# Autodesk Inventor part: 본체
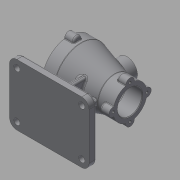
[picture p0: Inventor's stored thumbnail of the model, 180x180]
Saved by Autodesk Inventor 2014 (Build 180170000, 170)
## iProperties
Created: 2020-12
Part Number: 본체
Material: Generic
Document SubType Name: Modeling
Designer: kh
Density: 1 g/cm^3
Appearance: Default
Author: kh
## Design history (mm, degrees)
sketch "Sketch1"
  geometry: L1 (-65, -50)-(65, -50); L2 (65, -50)-(65, 50); L3 (65, 50)-(-65, 50); L4 (-65, 50)-(-65, -50); L5 (-65, -50)-(65, 50); L6 (65, -50)-(-65, 50); 1 further point
  constraints: 12 end point, 2 midpoint, 2 parallel, 1 horizontal, 1 perpendicular
  dimensions: "d0" = 130 distance of L2.end L3.end; "d1" = 100 distance of L1.end L2.end
extrude "Extrusion1" new body sketch "Sketch1" distance "d2" = 12; taper "d3" = 0 deg
sketch "Sketch2"
  geometry: L1 (-70.278, 82)-(64.917, 82); L2 (65, 0)-(-65, 0) reference; L3 (-50, 82)-(-50, 126); L4 (-50, 126)-(-30, 126); L5 (-30, 126)-(25, 109.5); L6 (25, 109.5)-(50, 109.5); L7 (50, 109.5)-(50, 82); L8 (-50, 82)-(50, 82); 1 further point
  constraints: 14 end point, 3 perpendicular, 2 point on line, 1 collinear, 1 horizontal, 1 parallel
  dimensions: "d4" = 82 distance between parallel lines of L2 L1; "d5" = 88 diameter of L4 L1; "d6" = 55 diameter of L6 L1; "d7" = 100 distance between parallel lines of L7 L3; "d8" = 50 distance from line of L3 point (0, 0); "d9" = 20 distance of L3.end L4.end; "d113" = 25 distance from line of L5.end L7
revolve "Revolution1" sketch "Sketch2" stored, may be unused: angle "d11" = 90 deg
sketch "Sketch3"
  geometry: L1 (-24, -4)-(24, -4); L2 (24, -4)-(24, 4); L3 (24, 4)-(-24, 4); L4 (-24, 4)-(-24, -4); L5 (-24, -4)-(24, 4); L6 (24, -4)-(-24, 4); 1 further point
  constraints: 12 end point, 2 midpoint, 2 parallel, 1 horizontal, 1 perpendicular
  dimensions: "d12" = 8 distance of L1.end L2.end; "d13" = 48 distance of L2.end L3.end
extrude "Extrusion2" join sketch "Sketch3" distance "d14" = 70.25; taper "d15" = 0 deg
sketch "Sketch4"
  geometry: L1 (9.974, 25)-(50.933, 25); L2 (12, -50)-(12, 50) reference; 1 further point
  constraints: 2 end point, 1 perpendicular
  dimensions: "d16" = 25 distance from line of point (0, 0) L1
feature "Rib1" sketch "Sketch4" dims "d17" = 1, "d18" = 8, "d19" = 0, "d20" = 0, "d21" = 1, "d22" = 1
sketch "Sketch5"
  geometry: L1 (8.739, -25)-(54.792, -25); 1 further point
  constraints: 2 end point, 1 horizontal
  dimensions: "d23" = 25 distance from line of L1 point (0, 0)
feature "Rib2" sketch "Sketch5" dims "d24" = 1, "d25" = 8, "d26" = 0, "d27" = 0, "d28" = 1, "d29" = 1
sketch "Sketch6"
  geometry: C1 r 7 at (0, 44); 3 further points
  constraints: 3 vertical alignment, 1 centre point, 2 other
  dimensions: "d30" = 14 diameter of C1
extrude "Extrusion3" join sketch "Sketch6" distance "d31" = 15; taper "d32" = 0 deg
pattern_circular "Circular Pattern1" dims angle "d34" = 360 deg
sketch "Sketch7"
  geometry: C1 r 7 at (0, 27.5); 2 further points
  constraints: 2 vertical alignment, 1 centre point, 1 other
  dimensions: "d36" = 14 diameter of C1
extrude "Extrusion4" join sketch "Sketch7" distance "d37" = 15; taper "d38" = 0 deg
pattern_circular "Circular Pattern2" dims angle "d40" = 360 deg
workplane "Work Plane1"
sketch "Sketch8"
  geometry: C1 r 17 at (0, 0); 1 further point
  constraints: 1 centre point, 1 coincident
  dimensions: "d43" = 34 diameter of C1
extrude "Extrusion5" join sketch "Sketch8" distance "d44" = 45; taper "d45" = 0 deg
sketch "Sketch10"
  geometry: C1 r 32 at (0, -44); A1 r 44 centre (0, -44) between (-6.978, -0.557) and (-43.443, -37.022) reference; 1 further point
  constraints: 1 centre point, 1 coincident
  dimensions: "d46" = 64 diameter of C1
extrude "Extrusion6" cut sketch "Sketch10" distance "d47" = 23; taper "d48" = 0 deg
sketch "Sketch11"
  geometry: C1 r 32 at (0, 0) reference; C2 r 26 at (0, 0); 1 further point
  constraints: 1 centre point, 1 coincident
  dimensions: "d49" = 52 diameter of C2
extrude "Extrusion7" cut sketch "Sketch11" distance "d50" = 47; taper "d51" = 0 deg
sketch "Sketch12"
  geometry: C1 r 26 at (0, 0) reference; C2 r 20 at (0, 0); 1 further point
  constraints: 1 centre point, 1 coincident
  dimensions: "d52" = 40 diameter of C2
extrude "Extrusion8" cut sketch "Sketch12" distance "d53" = 30; taper "d54" = 0 deg
hole "Hole1" diameter "d57" = 22; stored, may be unused: countersink angle "d61" = 90 deg, drill point angle "d63" = 0 deg; dims "d55" = 10, "d56" = 10, "d58" = 6, "d59" = 28, "d60" = 1, "d62" = 45
hole "Hole2" diameter "d66" = 4.134; stored, may be unused: countersink angle "d70" = 90 deg, drill point angle "d72" = 118 deg; dims "d64" = 10, "d65" = 10, "d67" = 9, "d68" = 28, "d69" = 1, "d71" = 11
pattern_circular "Circular Pattern3" dims angle "d74" = 360 deg
hole "Hole3" diameter "d78" = 4.134; stored, may be unused: countersink angle "d82" = 90 deg, drill point angle "d84" = 118 deg; dims "d76" = 10, "d77" = 10, "d79" = 9, "d80" = 28, "d81" = 1, "d83" = 11
pattern_circular "Circular Pattern4" dims angle "d86" = 360 deg
fillet "Fillet1" dims "d88" = 12
hole "Hole4" diameter "d91" = 10; stored, may be unused: countersink angle "d95" = 90 deg, drill point angle "d97" = 0 deg; dims "d92" = 10, "d93" = 28, "d94" = 1, "d96" = 11, "d98" = 10, "d99" = 10
pattern_linear "Rectangular Pattern1"
sketch "Sketch13"
  geometry: L1 (-65, 38)-(-65, -38) reference; L2 (-53, -50)-(53, -50) reference; 2 further points
  constraints: 1 other
  dimensions: "d104" = 65 distance from line of L1 point (0, -40); "d105" = 10 distance from line of L2 point (0, -40)
emboss "Emboss1" sketch "Sketch13" dims "d0" = 130, "d1" = 100, "d106" = 0.5, "d107" = 0
chamfer "Chamfer1" distance "d108" = 1; stored, may be unused: second distance "d109" = 2, angle "d110" = 45 deg
fillet "Fillet2" dims "d111" = 3
fillet "Fillet3" dims "d112" = 1
fillet "Fillet4" dims "d114" = 3
fillet "Fillet5" dims "d115" = 3
body "Solid1"
other parameters: "d42" = -82
